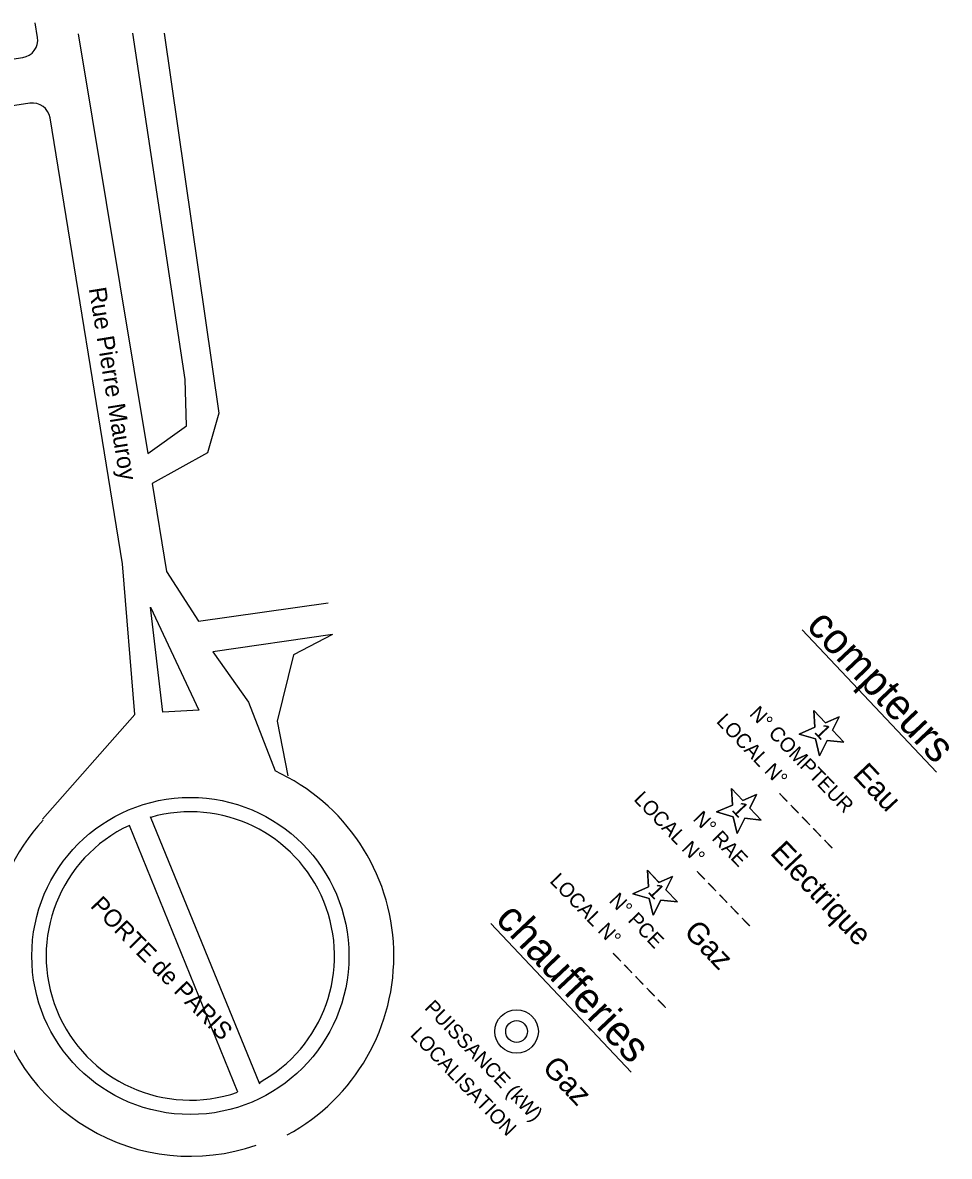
# Model space of a CAD drawing. Extents: x 703432 to 707394, y 7057985 to 7059523.
# Drawn here: x 704899.3 to 705059.1, y 7059200.3 to 7059395.7 of the extents above; entities that cross this region are included whole.
import ezdxf

# ---------------------------------------------------------------- set-up
doc = ezdxf.new("R2010")
doc.units = 0
for name, color, linetype in [('DH_TEXTE', 7, 'Continuous'), ('LIB_08', 7, 'Continuous'), ('VOIRIE_ROUTE', 7, 'Continuous')]:
    doc.layers.add(name, color=color, linetype=linetype)

msp = doc.modelspace()

# ---------------------------------------------------------------- linework, layer by layer
at = {"layer": 'LIB_08'}
for p, q in [((705033.72, 7059291.1), (705056.9, 7059266.53)), ((705037.72, 7059275.06), (705035.75, 7059277.15)), ((705035.75, 7059277.15), (705035.92, 7059274.28)), ((705040.09, 7059276.08), (705037.72, 7059275.06)), ((705038.93, 7059273.78), (705040.09, 7059276.08)), ((705035.92, 7059274.28), (705033.2, 7059273.11)), ((705040.9, 7059271.69), (705038.93, 7059273.78)), ((705036.72, 7059269.38), (705038.05, 7059272.02)), ((705038.05, 7059272.02), (705040.9, 7059271.69)), ((705023.49, 7059261.64), (705021.52, 7059263.72)), ((705021.52, 7059263.72), (705021.69, 7059260.86)), ((705025.86, 7059262.66), (705023.49, 7059261.64)), ((705024.7, 7059260.35), (705025.86, 7059262.66)), ((705021.69, 7059260.86), (705018.97, 7059259.68)), ((705026.67, 7059258.27), (705024.7, 7059260.35)), ((705022.49, 7059255.95), (705023.82, 7059258.6)), ((705023.82, 7059258.6), (705026.67, 7059258.27)), ((705009.02, 7059247.54), (705007.05, 7059249.63)), ((705007.05, 7059249.63), (705007.22, 7059246.76)), ((705011.38, 7059248.56), (705009.02, 7059247.54)), ((705010.23, 7059246.26), (705011.38, 7059248.56)), ((705007.22, 7059246.76), (705004.5, 7059245.59)), ((705004.5, 7059245.59), (705007.34, 7059244.74)), ((705007.34, 7059244.74), (705007.34, 7059244.74)), ((705007.34, 7059244.74), (705007.34, 7059244.74)), ((705007.34, 7059244.74), (705008.02, 7059241.86)), ((705008.02, 7059241.86), (705009.35, 7059244.5)), ((705009.35, 7059244.5), (705012.2, 7059244.17)), ((705012.2, 7059244.17), (705010.23, 7059246.26)), ((704980.05, 7059240.47), (705004.24, 7059214.82))]:
    msp.add_line(p, q, dxfattribs=at)
for points in [[(705035.75, 7059277.15), (705037.73, 7059275.06), (705040.09, 7059276.08), (705038.93, 7059273.78), (705040.9, 7059271.69), (705038.05, 7059272.02), (705036.72, 7059269.38), (705036.04, 7059272.26), (705033.2, 7059273.11), (705035.92, 7059274.28)], [(705021.52, 7059263.72), (705023.5, 7059261.64), (705025.86, 7059262.66), (705024.7, 7059260.35), (705026.67, 7059258.27), (705023.82, 7059258.6), (705022.49, 7059255.95), (705021.81, 7059258.84), (705018.97, 7059259.68), (705021.69, 7059260.86)], [(705007.05, 7059249.63), (705008.9, 7059247.67), (705009.02, 7059247.54), (705011.38, 7059248.56), (705010.23, 7059246.26), (705012.2, 7059244.17), (705009.35, 7059244.5), (705008.02, 7059241.86), (705007.34, 7059244.74), (705004.5, 7059245.59), (705007.22, 7059246.76)]]:
    msp.add_lwpolyline(points, close=True, dxfattribs=at)
for points in [[(705033.2, 7059273.11), (705036.04, 7059272.26), (705036.04, 7059272.26)], [(705036.04, 7059272.26), (705036.04, 7059272.26), (705036.72, 7059269.38)], [(705018.97, 7059259.68), (705021.81, 7059258.84), (705021.81, 7059258.83)], [(705021.81, 7059258.83), (705021.81, 7059258.84), (705022.49, 7059255.95)]]:
    msp.add_lwpolyline(points, dxfattribs=at)
for radius in [3.75, 1.88, 1.88]:
    msp.add_circle((704984.49, 7059221.84), radius, dxfattribs=at)
at = {"layer": 'VOIRIE_ROUTE'}
for p, q in [((704918.7, 7059276.45), (704902.74, 7059258.43)), ((704929.71, 7059277.25), (704923.51, 7059276.88)), ((704921.35, 7059258.9), (704940.18, 7059212.8)), ((704917.73, 7059257.42), (704936.38, 7059211.42))]:
    msp.add_line(p, q, dxfattribs=at)
for points in [[(704901.9, 7059393.2), (704901.51, 7059395.73)], [(704908.92, 7059393.82), (704920.91, 7059321.47), (704927.61, 7059326.25), (704927.35, 7059334.24), (704918.33, 7059393.95)], [(704923.74, 7059393.95), (704933.15, 7059328.44), (704931.22, 7059321.6), (704921.68, 7059316.32), (704924.13, 7059301.1), (704929.67, 7059292.59), (704951.98, 7059295.72)], [(704740.74, 7059343.69), (704767.97, 7059366.05), (704774, 7059369.35), (704782.46, 7059371.89), (704899.35, 7059389.72)], [(704900.6, 7059381.84), (704783.31, 7059363.81), (704773.95, 7059359.85), (704746.36, 7059337.47)], [(704918.7, 7059276.45), (704916.55, 7059302.47), (704904.07, 7059379.32)], [(704923.51, 7059276.88), (704921.37, 7059294.98), (704929.71, 7059277.25)], [(704952.74, 7059290.27), (704932.12, 7059287.3), (704938.25, 7059278.62), (704942.86, 7059266.74)], [(704952.74, 7059290.27), (704946.04, 7059286.78), (704943.2, 7059275.31), (704945.05, 7059265.9)]]:
    msp.add_lwpolyline(points, dxfattribs=at)
msp.add_circle((704928.25, 7059234.85), 27.33, dxfattribs=at)
for centre, radius, start, end in [((704898.89, 7059392.74), 3.05, 278.6767, 8.6767), ((704901.06, 7059378.83), 3.05, 9.2218, 98.7403), ((704928.25, 7059234.85), 35.08, 298.459, 65.3951), ((704928.25, 7059234.85), 34.53, 137.2612, 173.7773), ((704928.25, 7059234.85), 24.85, 298.459, 105.9703), ((704928.25, 7059234.85), 24.85, 115.0132, 289.1455), ((704928.25, 7059234.85), 34.53, 189.1939, 289.1455)]:
    msp.add_arc(centre, radius, start, end, dxfattribs=at)

# ---------------------------------------------------------------- texts
at = {"layer": 'DH_TEXTE'}
for s, rotation, p in [('Rue Pierre Mauroy', 279.2071, (704910.73, 7059349.9)), ('PORTE de PARIS', 314.4253, (704910.87, 7059243.35))]:
    msp.add_text(s, height=3, rotation=rotation, dxfattribs=at).set_placement(p)
at = {"layer": 'LIB_08'}
for s, height, rotation, p in [('compteurs', 5.25, 313.3307, (705034.24, 7059291.59)), ('N° COMPTEUR', 2.5, 313.9654, (705024.5, 7059276.45)), ('LOCAL N° _ _ _ _ _', 2.5, 313.9654, (705018.78, 7059275.18)), ('1', 2.65, 313.3307, (705035.67, 7059273.37)), ('Eau', 3.75, 313.3307, (705042.27, 7059265.93)), ('LOCAL N° _ _ _ _ _', 2.5, 313.9654, (705004.55, 7059261.76)), ('1', 2.65, 313.3307, (705021.44, 7059259.95)), ('N° RAE', 2.5, 313.9654, (705014.76, 7059258.37)), ('Electrique', 3.75, 313.3307, (705028.04, 7059252.51)), ('LOCAL N° _ _ _ _ _', 2.5, 313.9654, (704990.08, 7059247.66)), ('1', 2.65, 313.3307, (705006.97, 7059245.85)), ('N° PCE', 2.5, 313.9654, (705000.29, 7059244.27)), ('chaufferies', 5.25, 313.3307, (704980.64, 7059241.02)), ('Gaz', 3.75, 313.3307, (705013.15, 7059238.86)), ('PUISSANCE (kW)', 2.5, 313.9654, (704968.47, 7059225.79)), ('LOCALISATION', 2.5, 313.9654, (704966, 7059221.14)), ('Gaz', 3.75, 313.3307, (704988.74, 7059215.44))]:
    msp.add_text(s, height=height, rotation=rotation, dxfattribs=at).set_placement(p)

doc.saveas('drawing.dxf')
